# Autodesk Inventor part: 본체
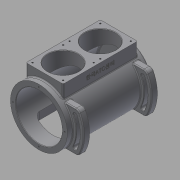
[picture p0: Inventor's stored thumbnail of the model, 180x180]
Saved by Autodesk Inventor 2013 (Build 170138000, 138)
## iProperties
Created: 2016-11
Part Number: 본체
Material: 일반
Document SubType Name: Modeling
Designer: mduedu
Density: 1 g/cm^3
Author: mduedu
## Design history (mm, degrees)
sketch "스케치1"
  geometry: C1 r 65 at (0, 0); 1 further point
  constraints: 1 centre point, 1 coincident
  dimensions: "d119" = 130 diameter of C1
extrude "돌출1" new body sketch "스케치1" distance "d3" = 98; taper "d4" = 0 deg; dims "d132" = 97, "d133" = 0
feature "쉘1" dims "d120" = 12, "d134" = 8
node "작업 평면2"
sketch "스케치13"
  geometry: L1 (42.5, 85)-(-42.5, 85); L2 (-42.5, 85)-(-42.5, -85); L3 (-42.5, -85)-(42.5, -85); L4 (42.5, -85)-(42.5, 85); 2 further points
  constraints: 8 end point, 2 parallel, 1 horizontal, 1 midpoint, 1 perpendicular, 1 vertical alignment
  dimensions: "d122" = 170 distance of L1.end L2.end; "d124" = 85 distance of L2.end L3.end; "d125" = 85 distance from line of point (0, 0) L1 (= 0.5 x d122)
extrude "돌출11" join sketch "스케치13" stored distance "d126" = 10; taper "d127" = 0 deg
sketch "스케치14"
  geometry: L1 (65, 97)-(-65, 97) reference; C1 r 35 at (0, 42.5); 1 further point
  constraints: 1 centre point, 1 vertical alignment
  dimensions: "d128" = 70 diameter of C1; "d129" = 54.5 distance from line of C1.centre L1
extrude "돌출12" cut sketch "스케치14" stored distance "d130" = 10; taper "d131" = 0 deg
sketch "스케치15"
  geometry: C1 r 53 at (0, 0) reference; 1 further point
extrude "돌출13" cut sketch "스케치15" stored distance "d135" = 10; taper "d136" = 0 deg
chamfer "모따기1" distance "d54" = 1; stored, may be unused: second distance "d55" = 2, angle "d56" = 45 deg
sketch "스케치8"
  geometry: C1 r 23 at (0, 0); C2 r 65 at (0, 0) reference; 1 further point
  constraints: 1 centre point, 1 concentric
  dimensions: "d57" = 46 diameter of C1
extrude "돌출8" join sketch "스케치8" distance "d58" = 14; taper "d59" = 0 deg
hole "구멍3" diameter "d62" = 24; stored, may be unused: countersink angle "d66" = 90 deg, drill point angle "d68" = 0 deg; dims "d63" = 6, "d64" = 28, "d65" = 8, "d67" = 14, "d169" = 10, "d170" = 10
fillet "모깎기11" dims "d69" = 3
fillet "모깎기12" dims "d70" = 3
fillet "모깎기13" dims "d71" = 0.3
chamfer "모따기2" distance "d72" = 1; stored, may be unused: second distance "d73" = 2, angle "d74" = 45 deg
node "작업 평면3"
sketch "스케치16"
  geometry: L1 (-42.5, -80)-(47.5, -80); L2 (-42.5, -80)-(21.14, -16.36); L3 (-42.5, -80)-(21.14, -143.64); L4 (3.462, -34.038)-(34.879, -34.038); L5 (3.462, -125.962)-(34.879, -125.962); A1 r 65 centre (-42.5, -80) between (3.462, -34.038) and (3.462, -125.962) reference; A2 r 90 centre (-42.5, -80) between (34.879, -125.962) and (34.879, -34.038); A3 r 90 centre (-42.5, -80) between (34.879, -34.038) and (34.879, -125.962); A4 r 65 centre (-42.5, -80) between (3.462, -125.962) and (3.462, -34.038); 1 further point
  constraints: 11 point on circle, 10 end point, 3 centre point, 2 parallel, 2 point on line, 1 coincident, 1 horizontal
  dimensions: "d140" = 45 deg angle of L3 L1; "d141" = 45 deg angle of L2 L1; "d142" = 25 radial gap between concentric circles of A1 A2
extrude "돌출14" join sketch "스케치16" distance "d143" = 15; taper "d144" = 0 deg
sketch "스케치17"
  geometry: L1 (-42.5, -80)-(34.414, -80); L2 (-42.5, -80)-(27.208, -47.495); L3 (-42.5, -80)-(27.208, -112.505); L4 (34.879, -34.038)-(3.462, -34.038) reference; L5 (3.462, -125.962)-(34.879, -125.962) reference; A1 r 65 centre (-42.5, -80) between (3.462, -34.038) and (3.462, -125.962) reference; A2 r 76.914 centre (-42.5, -80) between (19.17, -125.962) and (19.17, -34.038); A3 r 4 centre (27.208, -47.495) between (23.582, -49.185) and (30.833, -45.804); A4 r 4 centre (27.208, -112.505) between (30.833, -114.196) and (23.582, -110.815); A5 r 80.914 centre (-42.5, -80) between (30.833, -114.196) and (30.833, -45.804); A6 r 72.914 centre (-42.5, -80) between (23.582, -110.815) and (23.582, -49.185); 1 further point
  constraints: 13 point on circle, 6 end point, 5 centre point, 5 coincident, 3 midpoint, 2 point on line, 1 equal radius, 1 horizontal
  dimensions: "d145" = 25 deg angle of L1 L3; "d146" = 25 deg angle of L2 L1; "d147" = 8 diameter of A3
extrude "돌출15" cut sketch "스케치17" stored distance "d150" = 15; taper "d151" = 0 deg
fillet "모깎기17" dims "d152" = 10
fillet "모깎기18" dims "d153" = 2
fillet "모깎기19" dims "d154" = 2
chamfer "모따기4" distance "d155" = 1; stored, may be unused: second distance "d156" = 2, angle "d157" = 45 deg
fillet "모깎기20" dims "d159" = 3
fillet "모깎기21" dims "d160" = 3
fillet "모깎기22" dims "d161" = 3
node "작업 평면4"
sketch "스케치18"
  geometry: L1 (-42.5, 65)-(42.5, 65); L2 (42.5, 65)-(42.5, -65); L3 (42.5, -65)-(-42.5, -65); L4 (-42.5, -65)-(-42.5, 65); 2 further points
  constraints: 8 end point, 2 parallel, 1 horizontal, 1 midpoint, 1 perpendicular, 1 vertical alignment
  dimensions: "d162" = 130 distance of L1.end L2.end; "d164" = 85 distance of L2.end L3.end; "d165" = 65 distance from line of point (0, 0) L1 (= 0.5 x d162)
extrude "돌출16" cut sketch "스케치18" stored distance "d166" = 15; taper "d167" = 0 deg
fillet "모깎기23" dims "d168" = 10
fillet "모깎기24" dims "d173" = 3
sketch "스케치19"
  geometry: 4 further points
  constraints: 4 other
hole "구멍6" sketch "스케치19" at (0, -59), (59, 0), (-59, 0), (0, 59) diameter "d174" = 3.242; stored, may be unused: countersink angle "d178" = 90 deg, drill point angle "d180" = 120 deg; dims "d175" = 7, "d176" = 4, "d177" = 2, "d179" = 9
sketch "스케치20"
  geometry: L1 (35, -77.5)-(-35, -77.5); L2 (-35, -77.5)-(-35, -7.5); L3 (-35, -7.5)-(35, -7.5); L4 (35, -7.5)-(35, -77.5); L5 (35, -77.5)-(-35, -7.5); L6 (-35, -77.5)-(35, -7.5); C1 r 36 at (0, -42.5) reference; 5 further points
  constraints: 12 end point, 4 coincident, 2 midpoint, 2 parallel, 1 horizontal, 1 perpendicular
  dimensions: "d181" = 70 distance of L2.end L3.end; "d182" = 70 distance of L1.end L2.end
hole "구멍7" sketch "스케치20" at (-35, -77.5), (-35, -7.5), (35, -7.5), (35, -77.5) diameter "d183" = 3.242; stored, may be unused: countersink angle "d187" = 90 deg, drill point angle "d189" = 118 deg; dims "d184" = 7, "d185" = 4, "d186" = 2, "d188" = 9
sketch "스케치21"
  geometry: L1 (164, 0)-(0, 0) reference; L2 (-3, 0)-(-3, -24.649) reference; 3 further points
  constraints: 1 midpoint, 1 vertical alignment, 1 other
  dimensions: "d190" = 15 distance from line of point (82, -15) L1; "d191" = 85 distance from line of point (82, 0) L2 (derived)
feature "엠보싱2" sketch "스케치21" dims "d3" = 98, "d4" = 0, "d119" = 130, "d132" = 97, "d133" = 0, "d192" = 0.5, "d193" = 0
node "솔리드1"
mirror "대칭5"
mirror "대칭6"
mirror "대칭7"
